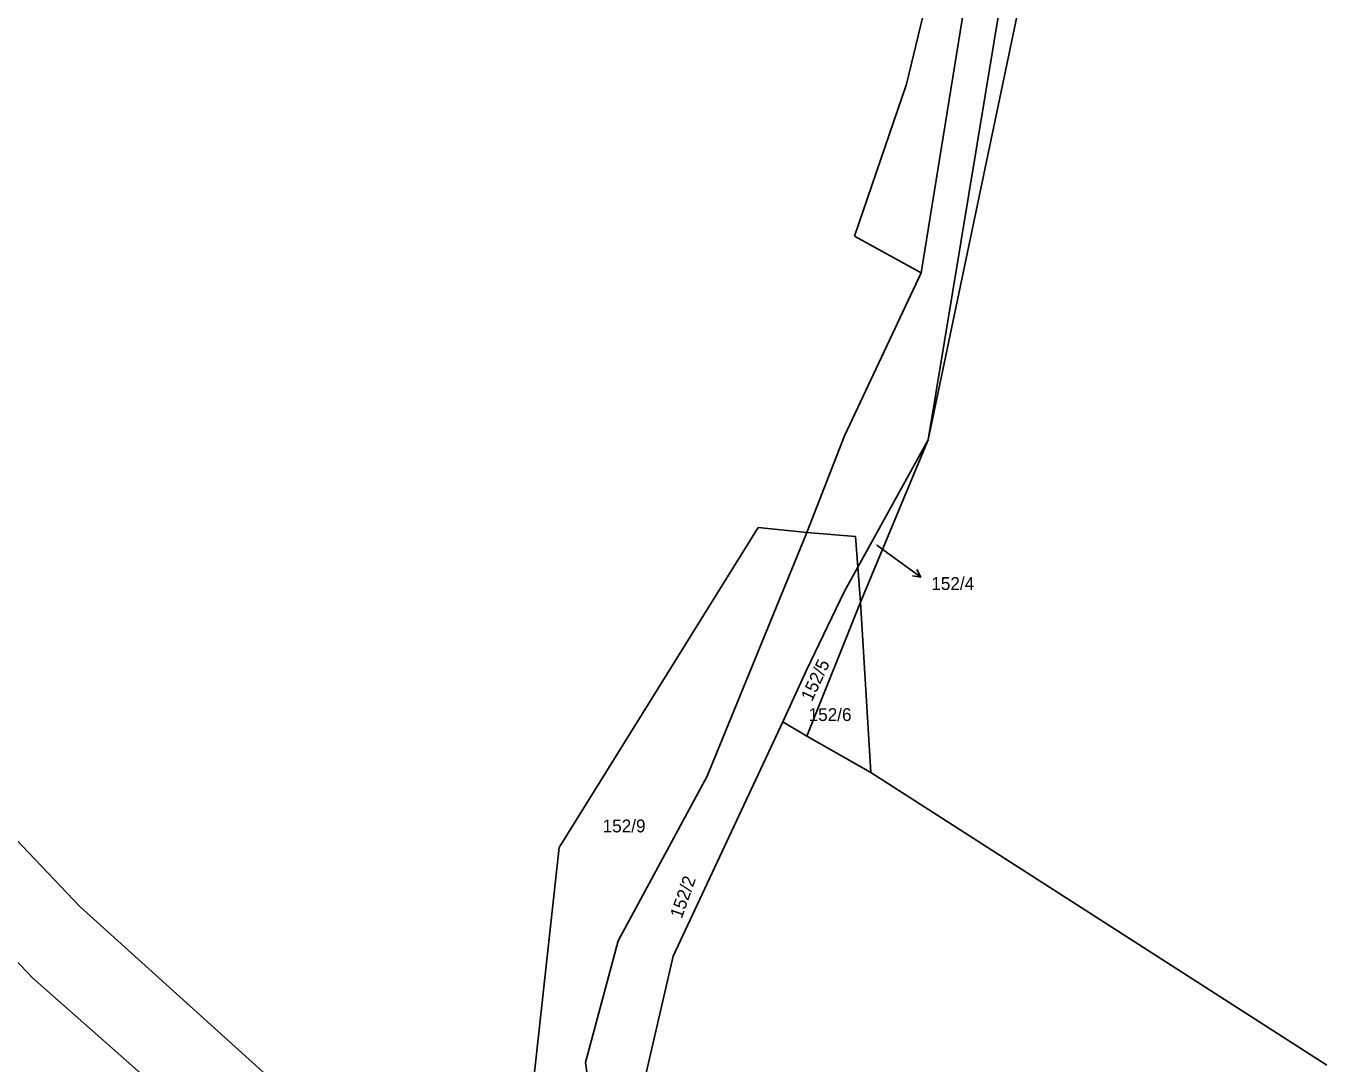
# Model space of a CAD drawing. Extents: x -852001 to -842497, y -1063614 to -1052182.
# Drawn here: x -849412.3 to -849240.1, y -1055892.4 to -1055755 of the extents above; entities that cross this region are included whole.
import ezdxf

# ---------------------------------------------------------------- set-up
doc = ezdxf.new("R2010")
doc.units = 0
for name, color, linetype in [('Default', 7, 'Continuous'), ('KN_HRANICE', 7, 'Continuous'), ('KN_PARCELY', 7, 'Continuous')]:
    doc.layers.add(name, color=color, linetype=linetype)

# ---------------------------------------------------------------- blocks, each defined once
blk = doc.blocks.new('10292')
at = {"layer": 'Default'}
blk.add_line((0, 3), (0, 0), dxfattribs=at)
blk.add_lwpolyline([(-0.5, 2), (0, 3), (0.5, 2)], dxfattribs=at)

msp = doc.modelspace()

# ---------------------------------------------------------------- linework, layer by layer
at = {"layer": 'KN_HRANICE'}
for p, q in [((-849295.76, -1055762.68), (-849279.58, -1055694.57)), ((-849295.76, -1055762.68), (-849279.58, -1055694.57)), ((-849285.94, -1055738.74), (-849293.83, -1055787.67)), ((-849285.94, -1055738.74), (-849293.83, -1055787.67)), ((-849292.9, -1055809.79), (-849281.34, -1055739.78)), ((-849292.9, -1055809.79), (-849281.34, -1055739.78)), ((-849280.75, -1055751.67), (-849292.9, -1055809.79)), ((-849280.75, -1055751.67), (-849292.9, -1055809.79)), ((-849302.66, -1055782.8), (-849295.76, -1055762.68)), ((-849302.66, -1055782.8), (-849295.76, -1055762.68)), ((-849293.83, -1055787.67), (-849302.66, -1055782.8)), ((-849293.83, -1055787.67), (-849302.66, -1055782.8)), ((-849293.83, -1055787.67), (-849304, -1055809.23)), ((-849293.83, -1055787.67), (-849304, -1055809.23)), ((-849304, -1055809.23), (-849308.99, -1055822.07)), ((-849304, -1055809.23), (-849308.99, -1055822.07)), ((-849292.9, -1055809.79), (-849302.21, -1055826.62)), ((-849292.9, -1055809.79), (-849302.21, -1055826.62)), ((-849301.86, -1055831.26), (-849292.9, -1055809.79)), ((-849301.86, -1055831.26), (-849292.9, -1055809.79)), ((-849341.76, -1055863.74), (-849315.43, -1055821.41)), ((-849341.76, -1055863.74), (-849315.43, -1055821.41)), ((-849315.43, -1055821.41), (-849308.99, -1055822.07)), ((-849315.43, -1055821.41), (-849308.99, -1055822.07)), ((-849308.99, -1055822.07), (-849322.16, -1055854.33)), ((-849308.99, -1055822.07), (-849322.16, -1055854.33)), ((-849308.99, -1055822.07), (-849302.52, -1055822.57)), ((-849308.99, -1055822.07), (-849302.52, -1055822.57)), ((-849302.52, -1055822.57), (-849302.21, -1055826.62)), ((-849302.52, -1055822.57), (-849302.21, -1055826.62)), ((-849302.21, -1055826.62), (-849303.98, -1055829.81)), ((-849302.21, -1055826.62), (-849303.98, -1055829.81)), ((-849302.21, -1055826.62), (-849301.86, -1055831.26)), ((-849302.21, -1055826.62), (-849301.86, -1055831.26)), ((-849303.98, -1055829.81), (-849309.03, -1055840.28)), ((-849303.98, -1055829.81), (-849309.03, -1055840.28)), ((-849308.99, -1055849.02), (-849301.86, -1055831.26)), ((-849308.99, -1055849.02), (-849301.86, -1055831.26)), ((-849301.86, -1055831.26), (-849300.5, -1055853.81)), ((-849301.86, -1055831.26), (-849300.5, -1055853.81)), ((-849309.03, -1055840.28), (-849312.13, -1055847.11)), ((-849309.03, -1055840.28), (-849312.13, -1055847.11)), ((-849312.13, -1055847.11), (-849326.67, -1055878.13)), ((-849312.13, -1055847.11), (-849326.67, -1055878.13)), ((-849308.99, -1055849.02), (-849312.13, -1055847.11)), ((-849308.99, -1055849.02), (-849312.13, -1055847.11)), ((-849300.5, -1055853.81), (-849308.99, -1055849.02)), ((-849300.5, -1055853.81), (-849308.99, -1055849.02)), ((-849300.5, -1055853.81), (-849240.11, -1055892.59)), ((-849300.5, -1055853.81), (-849240.11, -1055892.59)), ((-849322.16, -1055854.33), (-849333.93, -1055876.13)), ((-849322.16, -1055854.33), (-849333.93, -1055876.13)), ((-849418.81, -1055857.28), (-849405.22, -1055871.56)), ((-849418.81, -1055857.28), (-849405.22, -1055871.56)), ((-849428.32, -1055863.36), (-849411.46, -1055881.02)), ((-849428.32, -1055863.36), (-849411.46, -1055881.02)), ((-849347.35, -1055914.44), (-849341.76, -1055863.74)), ((-849347.35, -1055914.44), (-849341.76, -1055863.74)), ((-849405.22, -1055871.56), (-849336.98, -1055933.15)), ((-849405.22, -1055871.56), (-849336.98, -1055933.15)), ((-849333.93, -1055876.13), (-849338.26, -1055892.24)), ((-849333.93, -1055876.13), (-849338.26, -1055892.24)), ((-849326.67, -1055878.13), (-849330.6, -1055895.11)), ((-849326.67, -1055878.13), (-849330.6, -1055895.11)), ((-849411.46, -1055881.02), (-849317.98, -1055963.52)), ((-849411.46, -1055881.02), (-849317.98, -1055963.52)), ((-849338.26, -1055892.24), (-849334.75, -1055916.72)), ((-849338.26, -1055892.24), (-849334.75, -1055916.72))]:
    msp.add_line(p, q, dxfattribs=at)
at = {"layer": 'KN_PARCELY'}
msp.add_line((-849299.71, -1055823.72), (-849296.31, -1055826.19), dxfattribs=at)
msp.add_line((-849299.71, -1055823.72), (-849296.31, -1055826.19), dxfattribs=at)

# ---------------------------------------------------------------- block references
at = {"layer": 'KN_PARCELY', "rotation": -126.061332}
msp.add_blockref('10292', (-849296.31, -1055826.19), dxfattribs=at)
msp.add_blockref('10292', (-849296.31, -1055826.19), dxfattribs=at)

# ---------------------------------------------------------------- texts
at = {"layer": 'KN_PARCELY'}
for s, height, p in [('152/4', 0.1, (-849299.96, -1055823.72)), ('152/4', 0.1, (-849299.96, -1055823.72)), ('152/4', 1.7, (-849292.5, -1055829.66)), ('152/4', 1.7, (-849292.5, -1055829.66)), ('152/6', 1.7, (-849308.74, -1055847.01)), ('152/6', 1.7, (-849308.74, -1055847.01)), ('152/9', 1.7, (-849336.01, -1055861.75)), ('152/9', 1.7, (-849336.01, -1055861.75))]:
    msp.add_text(s, height=height, dxfattribs=at).set_placement(p)
for s, rotation, p in [('152/5', 65.088, (-849308.29, -1055844.52)), ('152/5', 65.088, (-849308.29, -1055844.52)), ('152/2', 70.474, (-849325.54, -1055873.27)), ('152/2', 70.474, (-849325.54, -1055873.27))]:
    msp.add_text(s, height=1.7, rotation=rotation, dxfattribs=at).set_placement(p)

doc.saveas('drawing.dxf')
